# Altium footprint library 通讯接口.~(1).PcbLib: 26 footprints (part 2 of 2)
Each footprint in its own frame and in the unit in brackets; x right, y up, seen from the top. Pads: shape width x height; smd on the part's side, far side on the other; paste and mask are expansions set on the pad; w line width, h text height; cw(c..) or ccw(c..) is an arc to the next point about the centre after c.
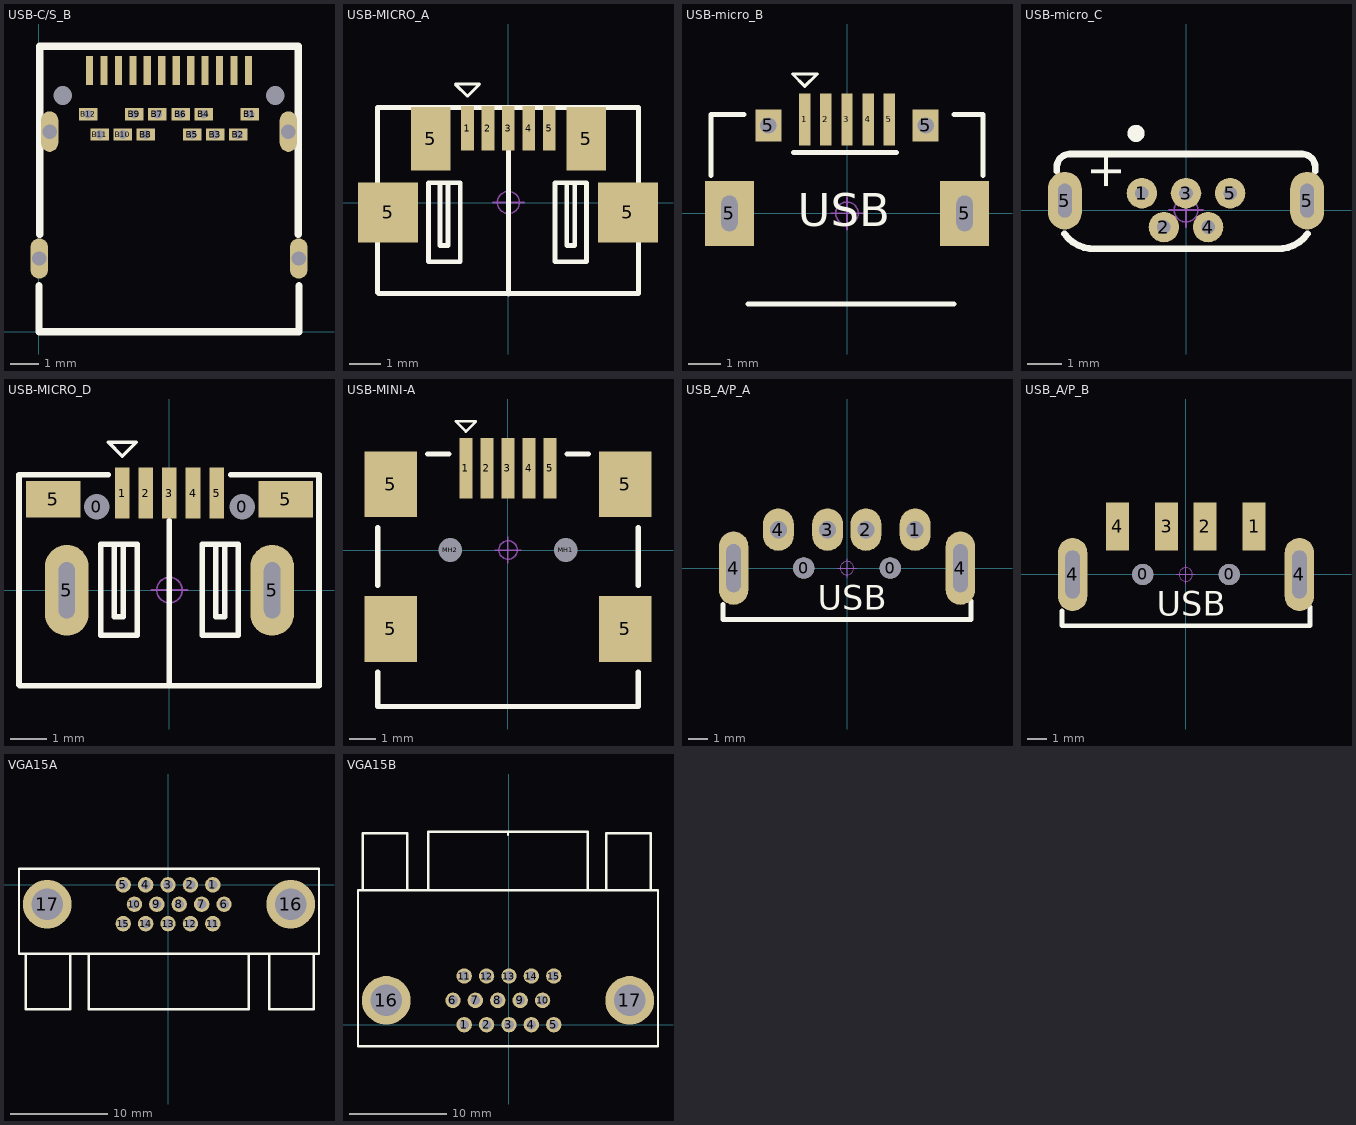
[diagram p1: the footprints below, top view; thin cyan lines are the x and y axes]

## USB-C/S_B [mm]
pads (30):
  rect 0.25x1 smd: A1(1.75,9.037) A2(2.25,9.037) A3(2.75,9.037) A4(3.25,9.037) A5(3.75,9.037) A6(4.25,9.037) A7(4.75,9.037) A8(5.25,9.037) A9(5.75,9.037) A10(6.25,9.037) A11(6.75,9.037) A12(7.25,9.037)
  rect 0.64x0.42 hole 0.3: B1(7.3,7.52) B2(6.9,6.82) B3(6.1,6.82) B4(5.7,7.52) B5(5.3,6.82) B6(4.9,7.52) B7(4.1,7.52) B8(3.7,6.82) B9(3.3,7.52) B10(2.9,6.82) B11(2.1,6.82) B12(1.7,7.52)
  oval 0.6x1.4 hole 0.5: ""(0.01,2.53) ""(0.37,6.92) ""(8.63,6.92) ""(8.99,2.53)
  round 0 hole 0.65: ""(0.825,8.17) ""(8.175,8.17)
Top Overlay:
  lines w0.254: 0,1.583 0,0 9,0 9,1.583 ; 0.025,3.37 0.025,9.87 8.975,9.87 8.975,3.37

## USB-MICRO_A [mm] "micro型USB ，5.9*8.2*2.5mm"
pads (9):
  rect 0.4x1.4 smd: 1(-1.296,2.355) 2(-0.648,2.355) 3(0,2.355) 4(0.648,2.355) 5(1.295,2.355)
  rect 1.9x1.9 smd: 5(-3.81,-0.312) 5(3.784,-0.312)
  rect 1.25x2 smd: 5(-2.464,2.025) 5(2.464,2.025)
Top Overlay:
  lines w0.1: -1.677,3.752 -1.296,3.371 -0.915,3.752 -1.677,3.752
  lines w0.152: -4.14,-2.852 -4.14,3.016 ; -4.115,-2.877 4.089,-2.877 ; -4.09,3.016 4.089,3.016 ; -2.165,0.628 -2.165,-1.357 -1.962,-1.357 -1.911,-1.357 -1.911,0.628 ; 0,-2.889 0,2.99 ; 1.848,0.628 1.848,-1.357 2.102,-1.357 2.102,0.628 ; 4.115,-2.877 4.115,3.016 ; -2.526,-1.872 -2.526,0.628 -1.526,0.628 -1.526,-1.872 -2.526,-1.872 ; 1.474,-1.872 2.474,-1.872 2.474,0.628 1.474,0.628 1.474,-1.872
Mechanical 15:
  circle w0.05: c0,0.006 r0.35
  lines w0.05: -0.5,0.006 0.5,0.006 ; 0,-0.494 0,0.506
3D body: height 2.69, standoff -0.24, extent -3.982,-2.772 3.982,2.65

## USB-micro_B [mm] "micro型USB ，5.7*7.8*2.5mm"
pads (9):
  rect 0.35x1.6 smd: 1(-1.3,2.9) 2(-0.65,2.9) 3(0,2.9) 4(0.65,2.9) 5(1.3,2.9)
  rect 1.5x2 hole 0.5 slot 1.1 at 90 deg: 5(-3.625,0) 5(3.625,0)
  rect 0.8x1 hole 0.5: 5(-2.425,2.71) 5(2.425,2.71)
Top Overlay:
  lines w0.1: -1.681,4.297 -0.919,4.297 -1.3,3.916 -1.681,4.297
  lines w0.152: -4.191,1.168 -4.191,3.048 -3.175,3.048 ; -3.048,-2.794 3.302,-2.794 ; -1.65,1.875 1.525,1.875 ; 3.302,3.048 4.191,3.048 4.191,1.168
  text "USB" at -1.524,-0.402 h1.02
Mechanical 15:
  circle w0.05: c0,0 r0.35
  lines w0.05: -0.5,0 0.5,0 ; 0,-0.5 0,0.5
3D body: height 2.8, standoff -0.95, extent -4.001,-2.71 4.001,2.89

## USB-micro_C [mm] "micro型USB ，5.7*7.8*2.5mm"
pads (7):
  round 0.9 hole 0.4: 1(-1.3,0.5) 2(-0.65,-0.5) 3(0,0.5) 4(0.65,-0.5) 5(1.3,0.5)
  oval 1x1.7 hole 0.4 slot 1 at 90 deg: 5(-3.575,0.28) 5(3.575,0.28)
Top Overlay:
  circle w0.254: c-1.473,2.261 r0.127
  lines w0.2: -3.81,1.143 -3.81,1.27 cw(c-3.429,1.27) -3.429,1.651 -3.175,1.651 -2.794,1.651 2.794,1.651 3.175,1.651 3.429,1.651 cw(c3.429,1.27) 3.81,1.27 3.81,1.143 ; -3.587,-0.697 ccw(c-2.718,-0.076) -2.667,-1.143 ; -2.629,-1.143 -2.413,-1.143 2.413,-1.143 2.667,-1.143 ccw(c2.718,-0.076) 3.587,-0.697
  text "+" at -1.905,0.559 h1.02
Mechanical 15:
  circle w0.05: c0,0 r0.35
  lines w0.05: -0.5,0 0.5,0 ; 0,-0.5 0,0.5
3D body: height 5.65, standoff -1.55, extent -4.001,-1.207 4.001,1.767

## USB-MICRO_D [mm] "micro型USB ，5.9*8.2*2.5mm"
pads (11):
  round 0.6 hole 0.7 unplated: 0(-2,2.294) 0(2,2.294)
  rect 0.4x1.4 smd: 1(-1.295,2.667) 2(-0.648,2.667) 3(0,2.667) 4(0.648,2.667) 5(1.295,2.667)
  rect 1.5x1 smd: 5(-3.2,2.5) 5(3.2,2.5)
  oval 1.2x2.5 hole 0.45 slot 1.55 at 90 deg: 5(-2.825,-0.006) 5(2.825,-0.006)
Top Overlay:
  lines w0.1: -1.676,4.064 -0.914,4.064 -1.295,3.683 -1.676,4.064
  lines w0.15: -4.14,3.175 -1.689,3.175 ; 0,-2.629 0,1.905 ; 1.689,3.175 4.115,3.175
  lines w0.152: -4.14,-2.603 -4.14,3.175 ; -4.115,-2.629 4.089,-2.629 ; -1.524,1.257 -1.524,-0.728 -1.321,-0.728 -1.27,-0.728 -1.27,1.257 ; 1.27,1.257 1.27,-0.728 1.524,-0.728 1.524,1.257 ; 4.115,-2.629 4.115,3.175 ; -1.885,-1.243 -1.885,1.257 -0.885,1.257 -0.885,-1.243 -1.885,-1.243 ; 0.896,-1.243 1.896,-1.243 1.896,1.257 0.896,1.257 0.896,-1.243
Mechanical 15:
  circle w0.05: c0,0 r0.35
  lines w0.05: -0.5,0 0.5,0 ; 0,-0.5 0,0.5
3D body: height 2.8, standoff -1.35, extent -4.001,-2.716 4.001,2.884

## USB-MINI-A [mm] "MINI型USB，7.9*7.5*4.1mm"
pads (11):
  rect 0.5x2.3 smd: 1(-1.6,3.108) 2(-0.8,3.108) 3(0,3.108) 4(0.8,3.108) 5(1.6,3.108)
  rect 2x2.5 smd: 5(-4.45,-3) 5(-4.45,2.5) 5(4.45,-3) 5(4.45,2.5)
  round 0.6 hole 0.9 unplated: MH1(2.2,0) MH2(-2.2,0)
Top Overlay:
  lines w0.1: -1.981,4.886 -1.6,4.505 -1.219,4.886 -1.981,4.886
  lines w0.2: -4.95,-4.65 -4.95,-5.95 4.95,-5.95 4.95,-4.65 ; -4.95,-1.35 -4.95,0.85 ; -3.05,3.65 -2.25,3.65 ; 2.25,3.65 3.05,3.65 ; 4.95,-1.35 4.95,0.85
Mechanical 15:
  circle w0.05: c0,0 r0.35
  lines w0.05: -0.5,0 0.5,0 ; 0,-0.5 0,0.5
3D body: height 3.95, standoff -0.7, extent -4.75,-6 4.75,3.7

## USB_A/P_A [mm] "A型USB 插头，20*13*4.5mm"
height 1.75
pads (8):
  round 1.1 hole 1.1: 0(-2.25,0) 0(2.25,0)
  oval 1.6x2.2 hole 0.9: 1(3.543,2) 2(0.987,2) 3(-1.013,2) 4(-3.569,2)
  oval 1.524x3.81 hole 0.762 slot 2.5 at 90 deg: 4(-5.9,0) 4(5.9,0)
Top Overlay:
  lines w0.254: -6.45,-1.9 -6.45,-2.667 6.45,-2.667 6.45,-1.7
  text "USB" at -1.524,-2.159 h1.27
Mechanical 15:
  circle w0.05: c0,0 r0.35
  lines w0.05: -0.5,0 0.5,0 ; 0,-0.5 0,0.5
3D body: height 3.25, standoff -2.52, extent -6.473,-17.9 6.473,2.105

## USB_A/P_B [mm] "A型USB 插头，20*13*4.5mm"
height 1.75
pads (8):
  round 1.1 hole 1.1: 0(-2.237,0) 0(2.263,0)
  rect 1.2x2.5 smd: 1(3.556,2.508) 2(1,2.508) 3(-1,2.508) 4(-3.556,2.508)
  oval 1.524x3.81 hole 0.762 slot 2.5 at 90 deg: 4(-5.887,0) 4(5.913,0)
Top Overlay:
  lines w0.254: -6.437,-1.9 -6.437,-2.667 6.463,-2.667 6.463,-1.7
  text "USB" at -1.511,-2.159 h1.27
Mechanical 15:
  circle w0.05: c0,0 r0.35
  lines w0.05: -0.5,0 0.5,0 ; 0,-0.5 0,0.5
3D body: height 3.25, standoff -2.52, extent -6.46,-17.9 6.487,2.7

## VGA15A [mm] "15针通讯接口"
pads (17):
  round 1.58 hole 1: 1(4.6,0) 2(2.3,0) 3(0,0) 4(-2.3,0) 5(-4.6,0) 6(5.75,-1.992) 7(3.45,-1.992) 8(1.15,-1.992) 9(-1.15,-1.992) 10(-3.45,-1.992) 11(4.6,-3.984) 12(2.3,-3.984) 13(0,-3.984) 14(-2.3,-3.984) 15(-4.6,-3.984)
  round 5 hole 3.25: 16(12.6,-1.992) 17(-12.4,-1.992)
Top Overlay:
  lines w0.254: -14.605,-7.087 -14.605,-12.751 -10.025,-12.751 -10.025,-7.087 ; -8.125,-7.061 -8.125,-12.751 8.275,-12.751 8.275,-7.137 ; 10.405,-7.061 10.405,-12.751 14.975,-12.751 14.975,-7.061 ; -15.3,-7.061 15.5,-7.061 15.5,1.629 -15.3,1.629 -15.3,-7.061
Mechanical 15:
  circle w0.05: c0,0 r0.35
  lines w0.05: -0.5,0 0.5,0 ; 0,-0.5 0,0.5
3D body: height 10.75, standoff -2.59, extent -15.397,-12.395 15.403,1.075

## VGA15B [mm] "15针通讯接口"
pads (17):
  round 1.58 hole 1: 1(-4.6,0) 2(-2.3,0) 3(0,0) 4(2.3,0) 5(4.6,0) 6(-5.75,2.5) 7(-3.45,2.5) 8(-1.15,2.5) 9(1.15,2.5) 10(3.45,2.5) 11(-4.6,5) 12(-2.3,5) 13(0,5) 14(2.3,5) 15(4.6,5)
  round 5 hole 3.25: 16(-12.6,2.5) 17(12.4,2.5)
Top Overlay:
  lines w0.254: -15.5,-2.2 -15.5,13.8 15.3,13.8 15.3,-2.2 -15.49,-2.2 -15.5,-2.19 ; -15,13.8 -15,19.67 -10.43,19.67 -10.43,13.82 ; -8.3,13.8 -8.3,19.8 8.1,19.8 8.1,13.8 ; -0.1,19.5 -0.1,19.8 ; 10,13.8 10,19.68 14.58,19.68 14.58,13.84
Mechanical 15:
  circle w0.05: c0,0 r0.35
  lines w0.05: -0.5,0 0.5,0 ; 0,-0.5 0,0.5
3D body: height 12.77, standoff -3.27, extent -15.655,-0.875 15.155,20.225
